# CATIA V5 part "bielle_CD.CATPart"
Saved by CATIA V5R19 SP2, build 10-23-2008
Part number: bielle_CD
Publications: "L_BD"
Bounding box of the stored display mesh (mm): x -110 to 210, y -10 to 10, z 0 to 10
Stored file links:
  D:\Dropbox\IAO_2011\MMS_GR2\IAO_2011_1521_alefevre\IAO_2011_1521_alefevre\bielle_CD.CATPart
  C:\Users\Aurélia\Desktop\COURS IFMA\IAO\assemblage_bielle.CATProduct
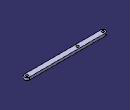
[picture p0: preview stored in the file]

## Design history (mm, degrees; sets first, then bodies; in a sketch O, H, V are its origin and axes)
Parameters
  L_BD = 100 mm
External parameters (linked from other documents)
  External.L_AB = 200 mm
Body1 (main body)
  Sketch1 on xy-plane, origin (0, 0, 0), H (1, 0, 0), V (0, 1, 0)
    construction line L1 (-100, 0) -> (200, 0)
    point P1 (-100, 0)
    point P2 (200, 0)
    line L2 (-100, 10) -> (200, 10)
    line L3 (200, -10) -> (-100, -10)
    arc A1 centre (200, 0) radius 10 from (200, 10) to (200, -10) cw
    arc A2 centre (-100, 0) radius 10 from (-100, -10) to (-100, 10) cw
    circle A3 centre (-100, 0) radius 5
    circle A4 centre (200, 0) radius 5
    circle A5 centre (0, 0) radius 5
    distance L1 L2 = 10
    radius A3 = 5
    radius A4 = 5
    radius A5 = 5
    distance P2 O = 200 {= External.L_AB}
    distance O P1 = 100 {= L_BD}
    coincidence: P1 H
    horizontal: L1 H
    tangency: A1 L2, A2 L2, A1 L3, A2 L3
  Pad1: profile Sketch1, direction (0, 0, 1), length 10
